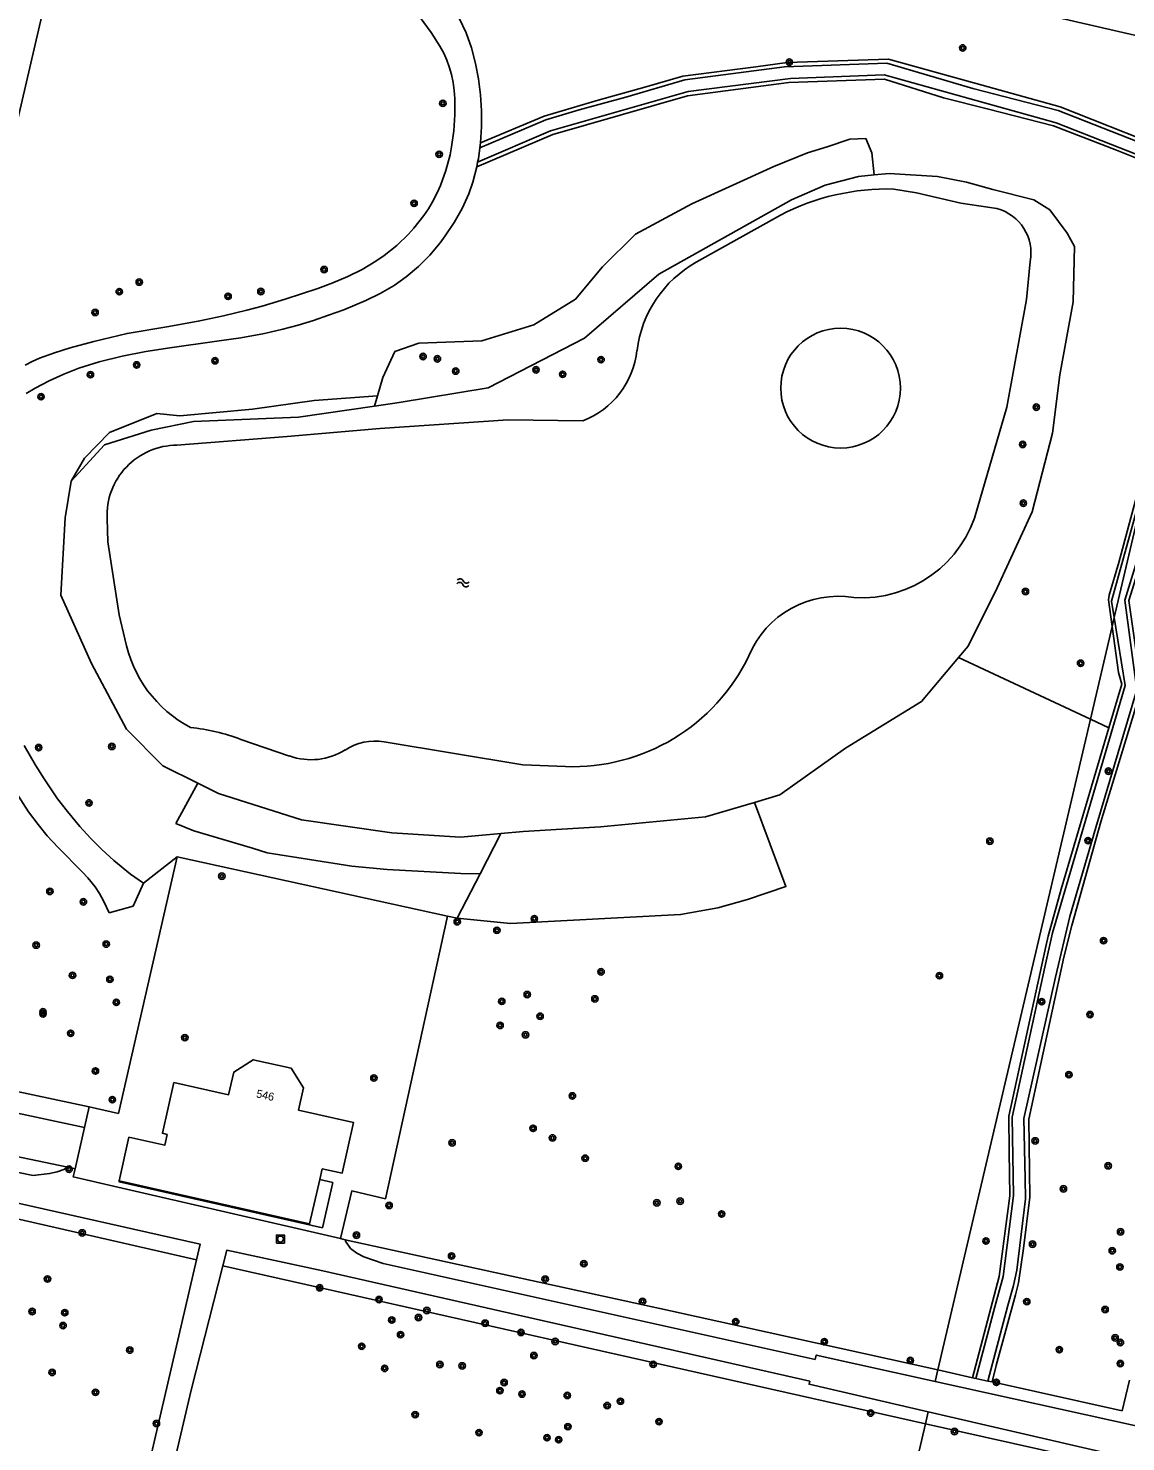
# Model space of a CAD drawing. Extents: x 128999 to 131010, y 395498 to 399007.
# Drawn here: x 129345.9 to 129482.9, y 396801.6 to 396978.2 of the extents above; entities that cross this region are included whole.
import ezdxf

# ---------------------------------------------------------------- set-up
doc = ezdxf.new("R2010")
doc.units = 0
for name, color, linetype in [('gg-anno-huisnummerreeks BGT', 7, 'Continuous'), ('gg-bbg-hoofdgebouw', 7, 'Continuous'), ('gg-bbg-onder overbouw', 7, 'Continuous'), ('gg-bbg-pand overbouw', 7, 'Continuous'), ('gg-knt-bronhoudergrens', 7, 'Continuous'), ('gg-knt-onverhard', 7, 'Continuous'), ('gg-kntw-bovenkant insteek waterloop', 7, 'Continuous'), ('gg-kntw-waterlijn', 7, 'Continuous'), ('gt-grn-groengrens', 7, 'Continuous'), ('gt-grn-vlakafsluiter', 7, 'Continuous'), ('gt-symb-boom', 7, 'Continuous'), ('gt-symb-rioolschacht', 7, 'Continuous'), ('gt-symb-watersymbool', 7, 'Continuous')]:
    doc.layers.add(name, color=color, linetype=linetype)

# ---------------------------------------------------------------- blocks, each defined once
blk = doc.blocks.new('gt0-BOOM')
at = {"layer": 'gt-symb-boom'}
for radius in [0.4, 0.2]:
    blk.add_circle((0, 0), radius, dxfattribs=at)
blk = doc.blocks.new('gt0-WA')
at = {"layer": 'gt-symb-watersymbool'}
for centre, start, end in [((-0.32, 0.02), 28.0725, 151.9275), ((0.43, 0.42), 208.0725, 331.9275), ((-0.32, -0.43), 28.0725, 151.9275), ((0.43, -0.03), 208.0725, 331.9275)]:
    blk.add_arc(centre, 0.425, start, end, dxfattribs=at)
blk = doc.blocks.new('gt0-RS')
at = {"layer": 'gt-symb-rioolschacht'}
blk.add_lwpolyline([(-0.5, -0.5), (0.5, -0.5), (0.5, 0.5), (-0.5, 0.5)], close=True, dxfattribs=at)
blk.add_circle((0, 0), 0.375, dxfattribs=at)

msp = doc.modelspace()

# ---------------------------------------------------------------- linework, layer by layer
at = {"layer": 'gg-bbg-hoofdgebouw'}
msp.add_line((129382.26, 396834.34), (129382.57, 396835.71), dxfattribs=at)
for points in [[(129382.57, 396835.71), (129385.07, 396835.16), (129386.48, 396841.48), (129379.63, 396843.01), (129380.25, 396845.81), (129378.7, 396848.26), (129373.97, 396849.32), (129371.52, 396847.77), (129370.89, 396844.94), (129364.04, 396846.47)], [(129364.04, 396846.47), (129362.62, 396840.13), (129363.22, 396839.99)], [(129363.22, 396839.99), (129362.92, 396838.64), (129358.44, 396839.64), (129357.23, 396834.2)]]:
    msp.add_lwpolyline(points, dxfattribs=at)
at = {"layer": 'gg-bbg-onder overbouw'}
msp.add_lwpolyline([(129357.23, 396834.2), (129381, 396828.8), (129382.26, 396834.34)], dxfattribs=at)
at = {"layer": 'gg-bbg-pand overbouw'}
msp.add_lwpolyline([(129382.26, 396834.34), (129383.89, 396833.97), (129382.6, 396828.32), (129357.2, 396834.08), (129357.23, 396834.2)], dxfattribs=at)
at = {"layer": 'gg-knt-bronhoudergrens'}
msp.add_line((129483.38, 396809.29), (129482.49, 396805.46), dxfattribs=at)
at = {"layer": 'gg-knt-onverhard'}
for p, q in [((129402.26, 396963.26), (129402.34, 396963.86)), ((129401.89, 396960.88), (129401.99, 396961.44)), ((129352.89, 396840.87), (129326.62, 396846.44)), ((129353.48, 396843.45), (129340.94, 396846.1)), ((129366.88, 396824.32), (129344.96, 396730)), ((129484.39, 396803.53), (129459.14, 396809.13)), ((129480.25, 396800.27), (129458.25, 396805.34))]:
    msp.add_line(p, q, dxfattribs=at)
for points in [[(129402.34, 396963.86), (129402.47, 396965.88), (129402.47, 396967.88), (129402.35, 396969.88), (129402.1, 396971.87), (129401.73, 396973.78), (129401.21, 396975.73), (129400.54, 396977.62), (129399.7, 396979.44), (129399.22, 396980.31), (129398.31, 396981.71), (129396.55, 396984.14), (129395.41, 396985.79), (129394.81, 396986.81), (129394.34, 396987.69), (129393.5, 396989.51), (129392.9, 396991.08), (129392.6, 396992.02), (129392.34, 396992.99), (129392.03, 396993.89), (129391.78, 396994.92), (129391.52, 396996.49)], [(129393.58, 396981.21), (129396.19, 396977.63), (129397.27, 396975.95), (129397.75, 396975.08), (129398.15, 396974.18), (129398.45, 396973.36), (129398.71, 396972.4), (129398.91, 396971.42), (129399.04, 396970.42), (129399.12, 396969.41), (129399.14, 396967.37), (129399, 396965.37), (129398.73, 396963.36), (129398.54, 396962.37), (129398.03, 396960.43), (129397.35, 396958.55), (129396.94, 396957.64), (129396.34, 396956.5), (129395.83, 396955.63), (129395.26, 396954.8), (129394.02, 396953.2), (129393.34, 396952.45), (129391.88, 396951.04), (129390.31, 396949.78), (129389.28, 396949.08), (129387.56, 396948.06), (129385.76, 396947.17), (129383.91, 396946.39), (129382.03, 396945.68), (129377.96, 396944.33), (129375.08, 396943.48), (129373.15, 396942.96), (129370.24, 396942.24), (129367.09, 396941.58), (129363.16, 396940.86), (129358.21, 396940.06), (129354.07, 396939.05), (129351.08, 396938.24), (129349.15, 396937.65), (129347.26, 396936.95), (129346.34, 396936.55), (129345.46, 396936.1)], [(129401.99, 396961.44), (129402.08, 396961.87), (129402.26, 396963.26)], [(129401.89, 396960.88), (129401.39, 396958.95), (129400.87, 396957.49), (129400.05, 396955.66), (129399.07, 396953.91), (129397.95, 396952.23), (129397.32, 396951.39), (129396.02, 396949.84), (129394.61, 396948.41), (129393.08, 396947.12), (129391.55, 396946.05), (129389.82, 396945.05), (129388.02, 396944.17), (129385.26, 396943.02), (129383.37, 396942.33), (129381.48, 396941.68), (129379.56, 396941.09), (129377.64, 396940.57), (129375.35, 396940.05), (129372.4, 396939.51), (129369.43, 396939.07), (129363.53, 396938.26), (129360.56, 396937.79), (129357.61, 396937.22), (129354.7, 396936.49), (129352.17, 396935.7), (129350.3, 396934.98), (129348.48, 396934.15), (129346.71, 396933.2), (129345.62, 396932.53)], [(129337.05, 396898.33), (129337.66, 396896.43), (129338.72, 396893.62), (129339.33, 396892.17), (129340.6, 396889.46), (129341.99, 396886.79), (129343.24, 396884.53), (129344.26, 396882.81), (129345.9, 396880.29), (129347.09, 396878.69), (129348.23, 396877.31), (129349.58, 396875.83), (129352.64, 396872.77), (129353.32, 396872.04), (129354.21, 396870.91), (129354.76, 396870.07), (129355.25, 396869.19), (129355.97, 396867.66)], [(129345.37, 396888.57), (129346.77, 396886.1), (129347.83, 396884.4), (129349.53, 396881.93), (129350.75, 396880.34), (129352.3, 396878.47), (129353.65, 396876.99), (129355.06, 396875.57), (129356.54, 396874.21), (129358.65, 396872.51), (129360.24, 396871.39)], [(129350.82, 396835.9), (129350.31, 396835.62), (129349.49, 396835.32), (129348.52, 396835.1), (129346.49, 396834.86), (129311.88, 396841.95), (129257.56, 396854.87), (129245.05, 396858.04)], [(129366.88, 396824.32), (129367.34, 396826.27), (129328.07, 396835.09), (129283.5, 396845.76), (129243.82, 396854.4)], [(129444.15, 396811.88), (129390.18, 396823.85), (129387.79, 396824.7), (129386.88, 396825.14), (129386.09, 396825.75), (129385.5, 396826.66), (129385.46, 396826.84)], [(129443.47, 396809.18), (129382.65, 396822.93), (129370.66, 396825.52), (129370.16, 396823.58)], [(129348.68, 396728.86), (129353.33, 396750), (129362.22, 396791), (129366.21, 396808.05), (129370.16, 396823.58)], [(129459.14, 396809.13), (129444.27, 396812.42), (129444.15, 396811.88)], [(129458.25, 396805.34), (129443.38, 396808.77), (129443.47, 396809.18)]]:
    msp.add_lwpolyline(points, dxfattribs=at)
at = {"layer": 'gg-kntw-bovenkant insteek waterloop'}
for points in [[(129497.77, 396974.01), (129494.74, 396974.87), (129418, 396992.51), (129404.36, 396995.46), (129398.33, 396996.84)], [(129462.05, 396899.59), (129463.24, 396901), (129466.88, 396908.29), (129471.25, 396917.76), (129473.8, 396927.6), (129474.71, 396934.89), (129476.35, 396944), (129476.53, 396950.93), (129475.62, 396952.57), (129473.44, 396955.49), (129471.43, 396956.76), (129466.33, 396958.04), (129463.05, 396958.95), (129459.41, 396959.68), (129453.4, 396960.04), (129451.49, 396959.86)], [(129451.49, 396959.86), (129449.57, 396959.68), (129445.38, 396958.58), (129441.2, 396956.76), (129424.62, 396947.47), (129415.33, 396939.45), (129403.31, 396933.25), (129392.2, 396931.43), (129389.1, 396930.98)], [(129389.1, 396930.98), (129379.63, 396929.61), (129366.51, 396929.06), (129361.23, 396927.97), (129355.4, 396926.15), (129351.21, 396921.59)], [(129351.21, 396921.59), (129350.49, 396917.03), (129349.94, 396907.37), (129353.76, 396898.81), (129358.14, 396890.61), (129362.69, 396886.05), (129367.03, 396883.88)], [(129436.56, 396881.47), (129439.74, 396882.41), (129447.93, 396888.24), (129457.41, 396894.07), (129462.05, 396899.59)], [(129367.03, 396883.88), (129369.61, 396882.59), (129379.99, 396879.31), (129391.29, 396877.67), (129399.85, 396877.12), (129404.9, 396877.59)], [(129404.9, 396877.59), (129407.68, 396877.85), (129417.33, 396878.4), (129430.45, 396879.67), (129436.56, 396881.47)]]:
    msp.add_lwpolyline(points, dxfattribs=at)
for start, end in [(0, 180), (180, 360)]:
    msp.add_arc((129447.32, 396933.22), 7.48, start, end, dxfattribs=at)
at = {"layer": 'gg-kntw-waterlijn'}
for p, q in [((129439.79, 396954.83), (129429.29, 396948.94)), ((129372.42, 396889.34), (129378.51, 396887.26))]:
    msp.add_line(p, q, dxfattribs=at)
for points in [[(129466.83, 396955.66), (129462.34, 396956.31), (129456.78, 396957.64), (129453.97, 396958.09)], [(129464.42, 396918.25), (129468.06, 396930.86), (129470.55, 396944.31), (129470.99, 396949.05)], [(129415.12, 396929.12), (129405.81, 396929.26), (129389.78, 396928.17), (129378.2, 396927.16), (129364.43, 396926.1)], [(129355.71, 396916.92), (129355.8, 396914.01), (129357.22, 396904.92), (129357.94, 396901.89)], [(129390.3, 396889.02), (129407.65, 396886.17), (129412.96, 396885.94)]]:
    msp.add_lwpolyline(points, dxfattribs=at)
for centre, radius, start, end in [((129453.15, 396929.23), 28.87, 88.3729, 117.5579), ((129465.38, 396950.13), 5.71, 349.135, 75.268), ((129436.43, 396936.15), 14.65, 119.1638, 172.9863), ((129411.28, 396939.08), 10.67, 291.0466, 353.8721), ((129364.48, 396917.32), 8.78, 90.3192, 182.6001), ((129449.93, 396921.99), 14.96, 266.365, 345.525), ((129447.02, 396895.13), 12.09, 80.6974, 157.3799), ((129373.57, 396904.9), 15.92, 190.9014, 242.1409), ((129413.81, 396910.41), 24.49, 268.0086, 334.2728), ((129363.72, 396866.64), 24.3, 69.0346, 84.3086), ((129381.19, 396894.71), 7.91, 250.1732, 302.3472), ((129389.12, 396882.41), 6.71, 79.9141, 123.397)]:
    msp.add_arc(centre, radius, start, end, dxfattribs=at)
at = {"layer": 'gt-grn-groengrens'}
for p, q in [((129389.47, 396932.27), (129389.1, 396930.98)), ((129481.5, 396904.55), (129486.48, 396925.81)), ((129481.24, 396903.43), (129481.5, 396904.55)), ((129478.52, 396891.85), (129481.24, 396903.43)), ((129462.05, 396899.59), (129478.52, 396891.85)), ((129459.47, 396810.56), (129478.52, 396891.85)), ((129478.52, 396891.85), (129480.82, 396890.77)), ((129364.28, 396878.83), (129367.03, 396883.88)), ((129404.9, 396877.59), (129402.3, 396872.53)), ((129402.3, 396872.53), (129399.45, 396867)), ((129366.88, 396824.32), (129232.68, 396855.1)), ((129457.9, 396803.85), (129370.16, 396823.58)), ((129459.14, 396809.13), (129459.47, 396810.56)), ((129459.47, 396810.56), (129463.8, 396809.6)), ((129463.8, 396809.6), (129464.22, 396809.51)), ((129464.22, 396809.51), (129465.69, 396809.18)), ((129465.69, 396809.18), (129466.25, 396809.06)), ((129466.25, 396809.06), (129482.49, 396805.46)), ((129457.9, 396803.85), (129458.25, 396805.34)), ((129479.92, 396798.9), (129457.9, 396803.85))]:
    msp.add_line(p, q, dxfattribs=at)
for points in [[(129354.23, 397008.45), (129335.94, 396929.88), (129254.69, 396948.95), (129247.23, 396917.14)], [(129493.75, 396956.86), (129486.94, 396963.55), (129474.75, 396968.38), (129453.29, 396974.32), (129440.66, 396973.9), (129436.75, 396973.35), (129427.63, 396972.18), (129422.87, 396970.81), (129417.04, 396969.21), (129410.28, 396967.2), (129402.34, 396963.86)], [(129493.64, 396956.38), (129486.68, 396963.11), (129474.48, 396967.92), (129463.83, 396970.67), (129453.07, 396973.82), (129440.3, 396973.38), (129427.85, 396971.73), (129420.48, 396969.58), (129414.66, 396968), (129410.5, 396966.75), (129402.26, 396963.26)], [(129401.89, 396960.88), (129411.37, 396964.91), (129428.2, 396969.72), (129440.85, 396971.39), (129452.79, 396971.81), (129460.15, 396969.5), (129465.64, 396968.12), (129473.89, 396965.97), (129481.76, 396962.93), (129485.52, 396961.44), (129492.13, 396954.95), (129492.71, 396952.39)], [(129492.94, 396953.37), (129492.47, 396955.34), (129485.48, 396961.97), (129474.23, 396966.36), (129452.77, 396972.35), (129441.08, 396971.91), (129428.3, 396970.26), (129411.08, 396965.38), (129401.99, 396961.44)], [(129451.49, 396959.86), (129451.2, 396962.6), (129450.48, 396964.39), (129448.46, 396964.33), (129445.63, 396963.36), (129443.2, 396962.61), (129438.97, 396960.92), (129428.75, 396956.24), (129421.72, 396952.47), (129417.59, 396948.39), (129414.22, 396944.33), (129408.99, 396941.14), (129402.49, 396939.15), (129394.66, 396938.85), (129391.66, 396937.78), (129390.13, 396934.57), (129389.47, 396932.27)], [(129466.25, 396809.06), (129466.76, 396811.14), (129469.17, 396819.96), (129469.55, 396821.43), (129470.16, 396825.73), (129470.97, 396832.17), (129470.82, 396841.91), (129475.2, 396862.12), (129476.2, 396866.08), (129479.81, 396879.02), (129484.04, 396892.84), (129484.78, 396895.45), (129484.85, 396895.86), (129483.3, 396906.67), (129485.88, 396914.95), (129486.57, 396917.63), (129488.36, 396925.12), (129493.46, 396938.63), (129496.36, 396941.99), (129496.45, 396942.22), (129496.39, 396947.33), (129494.44, 396956.19), (129493.75, 396956.86)], [(129465.69, 396809.18), (129468.21, 396818.62), (129468.91, 396821.11), (129469.31, 396823.01), (129470.4, 396831.93), (129470.36, 396834.42), (129470.18, 396841.96), (129474.16, 396859.65), (129475.96, 396867.23), (129479.19, 396878.34), (129484.3, 396895.53), (129482.8, 396906.75), (129484.32, 396911.59), (129486.15, 396918.15), (129487.54, 396923.76), (129487.82, 396925.37), (129492.93, 396938.68), (129496.15, 396942.32), (129495.89, 396947.07), (129494, 396956.03), (129493.64, 396956.38)], [(129389.47, 396932.27), (129381.57, 396931.68), (129373.86, 396930.61), (129364.79, 396929.77), (129361.94, 396930.07), (129356.03, 396927.67), (129352.9, 396924.49), (129351.21, 396921.59)], [(129487.41, 396929.77), (129486.13, 396926.43), (129485.95, 396925.85), (129482.06, 396911.42), (129480.86, 396907.34), (129480.76, 396906.79), (129481.24, 396903.43)], [(129481.5, 396904.55), (129481.17, 396906.61), (129486.39, 396925.56), (129486.48, 396925.81)], [(129464.22, 396809.51), (129466.57, 396818.46), (129467.63, 396822.22), (129468.93, 396832.35), (129468.74, 396842.13), (129472.83, 396860.87), (129473.78, 396865.16), (129482.85, 396896.07), (129481.5, 396904.55)], [(129481.24, 396903.43), (129482.04, 396897.7), (129482.43, 396896.23), (129480.82, 396890.77)], [(129480.82, 396890.77), (129474.85, 396870.64), (129473.22, 396864.76), (129472.93, 396863.47), (129468.31, 396842.29), (129468.35, 396837.86), (129468.44, 396832.31), (129467.14, 396822.25), (129463.8, 396809.6)], [(129436.56, 396881.47), (129440.48, 396870.95), (129435.7, 396869.32), (129431.97, 396868.31), (129427.33, 396867.45), (129406.08, 396866.34), (129399.45, 396867)], [(129402.3, 396872.53), (129399.88, 396872.6), (129390.69, 396873.07), (129386.28, 396873.49), (129375.71, 396875.16), (129373.85, 396875.75), (129366.55, 396877.9), (129364.28, 396878.83)], [(129234.38, 396862.34), (129245.27, 396860), (129277.06, 396852.22), (129312.27, 396843.95), (129350.82, 396835.9)], [(129385.46, 396826.84), (129426.06, 396817.96), (129459.47, 396810.56)], [(129348.68, 396728.86), (129434.2, 396702.7), (129457.9, 396803.85)]]:
    msp.add_lwpolyline(points, dxfattribs=at)
at = {"layer": 'gt-grn-vlakafsluiter'}
for p, q in [((129360.24, 396871.39), (129364.44, 396874.67)), ((129398.22, 396867.27), (129364.44, 396874.67)), ((129360.24, 396871.39), (129358.97, 396868.52)), ((129358.97, 396868.52), (129355.97, 396867.66)), ((129399.45, 396867), (129398.22, 396867.27)), ((129353.48, 396843.45), (129352.89, 396840.87)), ((129352.89, 396840.87), (129351.71, 396835.69)), ((129350.82, 396835.9), (129351.71, 396835.69)), ((129384.88, 396826.97), (129357.05, 396833.42)), ((129385.46, 396826.84), (129384.88, 396826.97))]:
    msp.add_line(p, q, dxfattribs=at)
for points in [[(129364.44, 396874.67), (129357.13, 396842.62), (129353.48, 396843.45)], [(129384.88, 396826.97), (129386.26, 396832.93), (129390.46, 396831.96), (129398.22, 396867.27)], [(129357.05, 396833.42), (129351.48, 396834.69), (129351.71, 396835.69)]]:
    msp.add_lwpolyline(points, dxfattribs=at)

# ---------------------------------------------------------------- block references
at = {"layer": 'gt-symb-boom'}
for p in [(129462.57, 396975.72), (129440.91, 396973.95), (129397.64, 396968.8), (129397.18, 396962.43), (129394.05, 396956.31), (129382.81, 396948.03), (129359.72, 396946.47), (129357.23, 396945.27), (129370.82, 396944.69), (129374.92, 396945.29), (129354.21, 396942.68), (129395.17, 396937.17), (129396.96, 396936.88), (129417.4, 396936.78), (129359.4, 396936.12), (129369.19, 396936.64), (129399.25, 396935.35), (129409.28, 396935.51), (129412.6, 396934.95), (129353.63, 396934.9), (129347.46, 396932.15), (129471.76, 396930.84), (129470.06, 396926.19), (129470.14, 396918.85), (129470.4, 396907.81), (129477.29, 396898.85), (129347.16, 396888.32), (129356.3, 396888.46), (129480.76, 396885.37), (129353.45, 396881.4), (129478.22, 396876.69), (129465.96, 396876.62), (129370.04, 396872.25), (129348.57, 396870.35), (129352.75, 396869.05), (129399.44, 396866.56), (129409.07, 396866.93), (129404.39, 396865.49), (129346.85, 396863.64), (129355.6, 396863.77), (129480.16, 396864.19), (129351.39, 396859.86), (129356.06, 396859.36), (129417.4, 396860.3), (129459.66, 396859.82), (129408.18, 396857.46), (129356.86, 396856.49), (129405, 396856.61), (129416.63, 396856.92), (129472.43, 396856.57), (129347.7, 396855.3), (129347.71, 396855.04), (129409.79, 396854.75), (129478.47, 396854.96), (129351.16, 396852.62), (129365.42, 396852.08), (129404.79, 396853.61), (129407.96, 396852.43), (129354.25, 396847.91), (129389.03, 396847.04), (129475.83, 396847.45), (129356.36, 396844.33), (129413.82, 396844.8), (129408.91, 396840.75), (129398.8, 396838.94), (129411.34, 396839.55), (129471.62, 396839.18), (129415.42, 396837.01), (129480.73, 396836.07), (129350.96, 396835.65), (129427.05, 396836), (129475.15, 396833.19), (129390.93, 396831.12), (129424.37, 396831.44), (129427.28, 396831.65), (129432.46, 396830.05), (129352.6, 396827.69), (129386.85, 396827.4), (129482.28, 396827.82), (129465.47, 396826.67), (129471.29, 396826.28), (129481.24, 396825.46), (129398.73, 396824.8), (129415.25, 396823.84), (129348.27, 396821.93), (129410.42, 396821.92), (129482.2, 396823.43), (129382.26, 396820.83), (129389.67, 396819.36), (129422.58, 396819.13), (129470.57, 396819.1), (129346.34, 396817.87), (129350.42, 396817.72), (129391.26, 396816.8), (129394.6, 396817.11), (129395.64, 396817.99), (129434.22, 396816.6), (129480.35, 396818.11), (129350.21, 396816.11), (129392.36, 396814.97), (129402.92, 396816.4), (129407.4, 396815.25), (129387.51, 396813.52), (129411.67, 396814.12), (129445.29, 396814.09), (129474.63, 396813.1), (129481.6, 396814.58), (129482.26, 396813.99), (129358.54, 396813.05), (129409.01, 396812.36), (129456.02, 396811.75), (129482.25, 396811.36), (129348.84, 396810.26), (129390.37, 396810.76), (129397.27, 396811.25), (129400.05, 396811.07), (129423.91, 396811.27), (129354.26, 396807.77), (129404.77, 396807.98), (129405.29, 396808.99), (129466.77, 396809.02), (129407.53, 396807.55), (129413.18, 396807.38), (129418.16, 396806.11), (129419.82, 396806.65), (129394.18, 396804.98), (129451.08, 396805.18), (129361.87, 396803.87), (129402.16, 396802.73), (129413.26, 396803.48), (129424.64, 396804.11), (129461.54, 396802.88), (129410.65, 396802.1), (129412.11, 396801.85)]:
    msp.add_blockref('gt0-BOOM', p, dxfattribs=at)
at = {"layer": 'gt-symb-rioolschacht'}
msp.add_blockref('gt0-RS', (129377.36, 396826.92), dxfattribs=at)
at = {"layer": 'gt-symb-watersymbool', "rotation": -7.700655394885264}
msp.add_blockref('gt0-WA', (129400.11, 396908.92), dxfattribs=at)

# ---------------------------------------------------------------- texts
at = {"layer": 'gg-anno-huisnummerreeks BGT'}
msp.add_text('546', height=1, rotation=347.4, dxfattribs=at).set_placement((129374.27, 396844.64))

doc.saveas('drawing.dxf')
